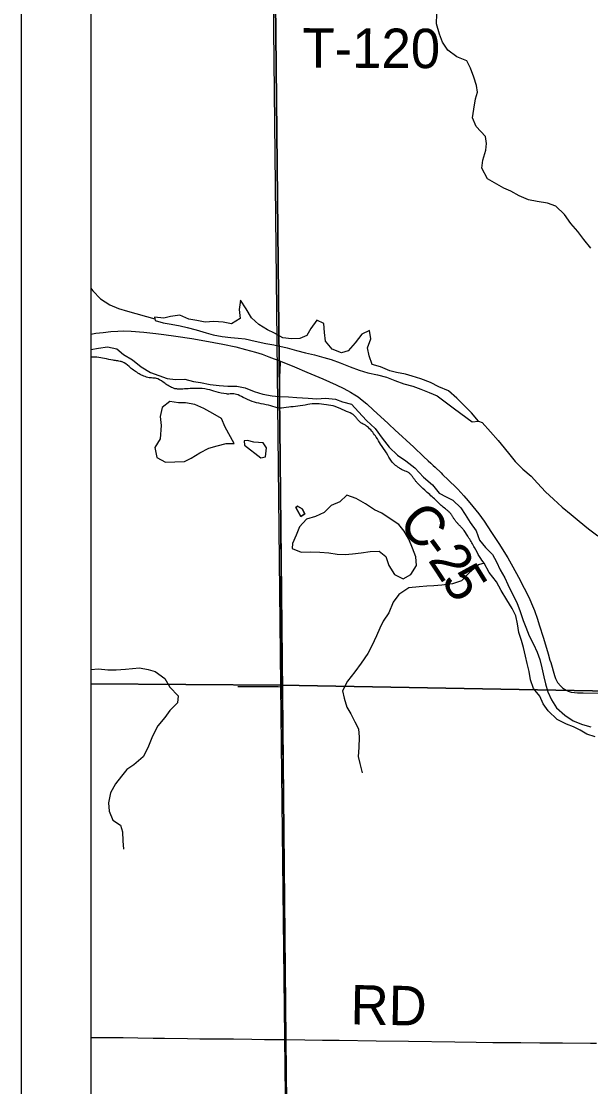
# Model space of a CAD drawing. Extents: x 0 to 1391, y -24 to 440.
# Drawn here: x 340 to 356.41, y 297.63 to 328.34 of the extents above; entities that cross this region are included whole.
import ezdxf

# ---------------------------------------------------------------- set-up
doc = ezdxf.new("R2010")
doc.units = 0
for name, color, linetype in [('GM_X_County_Road', 7, 'Continuous'), ('GM_X_County_Road_Text', 7, 'Continuous'), ('GM_X_Major_River', 7, 'Continuous'), ('GM_X_Minor_Lake', 7, 'Continuous'), ('GM_X_Minor_River', 7, 'Continuous'), ('GM_X_Section', 7, 'Continuous'), ('GM_X_Township', 7, 'Continuous'), ('GM_X_Township_Road', 7, 'Continuous'), ('GM_X_Township_Road_Text', 7, 'Continuous'), ('SH_Data', 7, 'Continuous')]:
    doc.layers.add(name, color=color, linetype=linetype)

msp = doc.modelspace()

# ---------------------------------------------------------------- linework, layer by layer
at = {"layer": 'GM_X_County_Road'}
for points in [[(342, 319.32), (342.146, 319.346), (342.355, 319.374), (342.577, 319.398), (342.787, 319.412), (342.96, 319.413), (343.17, 319.404), (343.528, 319.375), (343.874, 319.343), (344.108, 319.315), (344.452, 319.266), (344.919, 319.195), (345.286, 319.133), (345.811, 319.032), (346.187, 318.952), (346.464, 318.884), (346.751, 318.804), (346.94, 318.744), (347.138, 318.672), (347.476, 318.548)], [(347.522, 309.15), (347.51, 309.729), (347.5, 310.672), (347.493, 311.369), (347.495, 311.84), (347.492, 312.522), (347.487, 312.957), (347.484, 313.268), (347.481, 313.839), (347.481, 314.175), (347.481, 314.336), (347.48, 314.472), (347.475, 314.72), (347.472, 314.819), (347.467, 315.204), (347.459, 316.086), (347.454, 316.72), (347.451, 317.117), (347.45, 317.689), (347.452, 318.125), (347.459, 318.25), (347.476, 318.548)], [(347.476, 318.548), (347.874, 318.376), (348.231, 318.229), (348.688, 318.033), (349.075, 317.861), (349.298, 317.751), (349.485, 317.65), (349.614, 317.573), (349.708, 317.512), (349.828, 317.422), (349.962, 317.31), (350.156, 317.134), (350.565, 316.752), (350.601, 316.718), (350.766, 316.567), (351.312, 316.06), (351.596, 315.798), (351.732, 315.671), (351.804, 315.603), (351.875, 315.534), (351.93, 315.483), (352.101, 315.322), (352.142, 315.281), (352.184, 315.241), (352.28, 315.147), (352.579, 314.85), (352.759, 314.659), (352.883, 314.52), (353.019, 314.357), (353.186, 314.14), (353.339, 313.928), (353.557, 313.609), (353.765, 313.285), (354.021, 312.872), (354.172, 312.614), (354.334, 312.32), (354.5, 312), (354.637, 311.72), (354.708, 311.561), (354.79, 311.352), (354.878, 311.106), (354.932, 310.94), (355.05, 310.56), (355.184, 310.106), (355.236, 309.927), (355.26, 309.857), (355.366, 309.487), (355.399, 309.395), (355.434, 309.318), (355.459, 309.278), (355.555, 309.171), (355.599, 309.129), (355.657, 309.086), (355.709, 309.056), (355.762, 309.029), (355.854, 309.003), (355.951, 308.99), (356.036, 308.985), (356.197, 308.981), (356.657, 308.973)], [(347.627, 298.985), (347.626, 299.082), (347.613, 300.337), (347.603, 301.294), (347.598, 301.816), (347.586, 303.207), (347.579, 304.052), (347.574, 304.363), (347.566, 305.046), (347.565, 305.431), (347.56, 306.052), (347.551, 306.673), (347.536, 307.705), (347.533, 308.239), (347.532, 308.512), (347.524, 309.083), (347.522, 309.15)], [(347.727, 288.918), (347.727, 289.043), (347.723, 289.714), (347.709, 290.844), (347.702, 291.491), (347.694, 292.895), (347.684, 293.59), (347.674, 294.696), (347.656, 295.603), (347.651, 296.262), (347.635, 297.964), (347.629, 298.573), (347.627, 298.985)]]:
    msp.add_lwpolyline(points, dxfattribs=at)
at = {"layer": 'GM_X_Major_River'}
for points in [[(342, 318.879), (342.222, 318.918), (342.488, 318.952), (342.753, 318.902), (342.947, 318.74), (343.203, 318.577), (343.457, 318.383), (343.72, 318.212), (343.961, 318.132), (344.203, 318.045), (344.445, 318.018), (344.71, 318.022), (344.967, 317.957), (345.164, 317.931), (345.443, 317.873), (345.708, 317.846), (345.958, 317.82), (346.209, 317.823), (346.458, 317.774), (346.714, 317.671), (346.963, 317.591), (347.228, 317.542), (347.425, 317.523), (347.698, 317.519), (347.94, 317.5), (348.266, 317.479), (348.523, 317.46), (348.766, 317.479), (349.062, 317.444), (349.258, 317.372), (349.514, 317.308), (349.716, 317.084), (349.954, 316.83), (350.201, 316.598), (350.401, 316.322), (350.609, 316.068), (350.848, 315.836), (351.081, 315.673), (351.343, 315.464), (351.596, 315.201), (351.858, 314.977), (352.044, 314.739), (352.247, 314.629), (352.442, 314.535), (352.674, 314.318), (352.792, 314.119), (352.94, 313.889), (353.111, 313.651), (353.212, 313.384), (353.383, 313.176), (353.585, 312.975), (353.695, 312.761), (353.805, 312.531), (353.938, 312.301), (354.026, 312.102), (354.136, 311.865), (354.283, 311.582), (354.377, 311.33), (354.471, 311.063), (354.544, 310.872), (354.639, 310.627), (354.764, 310.39), (354.866, 310.153), (354.946, 309.946), (355.003, 309.703), (355.067, 309.443), (355.109, 309.238), (355.174, 309.009), (355.284, 308.779), (355.424, 308.549), (355.671, 308.34), (355.911, 308.177), (356.175, 308.066), (356.416, 308.002)], [(356.547, 307.713), (356.306, 307.794), (356.111, 307.911), (355.916, 307.999), (355.712, 308.078), (355.45, 308.213), (355.189, 308.46), (355.041, 308.668), (354.947, 308.882), (354.769, 309.106), (354.676, 309.358), (354.643, 309.602), (354.579, 309.831), (354.53, 310.037), (354.474, 310.288), (354.417, 310.494), (354.346, 310.723), (354.305, 310.975), (354.257, 311.203), (354.147, 311.418), (354, 311.663), (353.831, 311.932), (353.699, 312.185), (353.485, 312.455), (353.346, 312.716)]]:
    msp.add_lwpolyline(points, dxfattribs=at)
msp.add_spline([(353.346, 312.716), (353.213, 312.908), (353.066, 313.169), (352.905, 313.445), (352.765, 313.66), (352.709, 313.729), (352.648, 313.794), (352.586, 313.857), (352.528, 313.923), (352.483, 313.986), (352.442, 314.052), (352.4, 314.117), (352.35, 314.177), (352.291, 314.232), (352.228, 314.283), (352.104, 314.387), (351.911, 314.572), (351.635, 314.82), (351.419, 315.03), (351.363, 315.095), (351.313, 315.165), (351.262, 315.235), (351.204, 315.299), (351.141, 315.343), (351.069, 315.374), (350.995, 315.404), (350.927, 315.441), (350.857, 315.489), (350.789, 315.539), (350.673, 315.658), (350.526, 315.897), (350.357, 316.15), (350.232, 316.35), (350.009, 316.627), (349.952, 316.674), (349.888, 316.713), (349.823, 316.75), (349.762, 316.791), (349.705, 316.85), (349.653, 316.915), (349.598, 316.977), (349.532, 317.023), (349.321, 317.118), (349.051, 317.237), (348.794, 317.288), (348.521, 317.316), (348.256, 317.29), (347.967, 317.243), (347.708, 317.217), (347.435, 317.192), (347.193, 317.257), (346.914, 317.315), (346.657, 317.381), (346.394, 317.5), (346.199, 317.587), (346.13, 317.603), (346.057, 317.602), (345.983, 317.596), (345.911, 317.6), (345.616, 317.658), (345.368, 317.731), (345.065, 317.76), (344.807, 317.749), (344.606, 317.737), (344.505, 317.739), (344.455, 317.745), (344.405, 317.757), (344.265, 317.823), (344.135, 317.906), (343.933, 318.031), (343.865, 318.053), (343.791, 318.058), (343.717, 318.061), (343.646, 318.074), (343.571, 318.1), (343.498, 318.128), (343.36, 318.201), (343.106, 318.388), (342.911, 318.521), (342.878, 318.529), (342.846, 318.537), (342.779, 318.549), (342.647, 318.571), (342.398, 318.621), (342.178, 318.655), (342, 318.654)], degree=3, dxfattribs=at)
at = {"layer": 'GM_X_Minor_Lake'}
for p, q in [((352.995, 316.796), (353.177, 316.816)), ((346.426, 316.248), (346.438, 316.118))]:
    msp.add_line(p, q, dxfattribs=at)
for points in [[(353.177, 316.816), (352.976, 317.054), (352.767, 317.27), (352.559, 317.479), (352.319, 317.687), (352.033, 317.806), (351.8, 317.931), (351.513, 318.035), (351.272, 318.107), (351.076, 318.171), (350.819, 318.22), (350.622, 318.269), (350.351, 318.38), (350.117, 318.444), (350.03, 318.696), (349.981, 318.932), (350.076, 319.189), (350.042, 319.432), (349.813, 319.322), (349.627, 319.075), (349.418, 318.843), (349.228, 318.785), (348.964, 318.888), (348.77, 319.119), (348.737, 319.37), (348.718, 319.628), (348.522, 319.723), (348.344, 319.482), (348.235, 319.287), (348.028, 319.199), (347.793, 319.188), (347.536, 319.214), (347.295, 319.347), (347.1, 319.449), (346.852, 319.605), (346.635, 319.791), (346.48, 320.051), (346.317, 320.297), (346.282, 320.031), (346.309, 319.773), (346.056, 319.617), (345.822, 319.667), (345.549, 319.686), (345.298, 319.667), (345.064, 319.717), (344.829, 319.751), (344.566, 319.869), (344.3, 319.827), (344.11, 319.785), (343.837, 319.812)], [(343.837, 319.812), (343.858, 319.713), (344.085, 319.648), (344.319, 319.614), (344.584, 319.565), (344.78, 319.516), (345.037, 319.451), (345.331, 319.356), (345.527, 319.307), (345.792, 319.257), (346.042, 319.223), (346.254, 319.204), (346.451, 319.186), (346.745, 319.121), (347.048, 319.048), (347.275, 319.014), (347.668, 318.931), (347.932, 318.851), (348.196, 318.786), (348.453, 318.722), (348.717, 318.649), (348.929, 318.592), (349.193, 318.497), (349.479, 318.379), (349.735, 318.283), (349.992, 318.211), (350.264, 318.153), (350.528, 318.081), (350.769, 317.986), (351.026, 317.891), (351.282, 317.818), (351.516, 317.738), (351.757, 317.636), (351.991, 317.541), (352.485, 317.169), (352.995, 316.796)], [(346.133, 316.171), (345.872, 316.645), (345.771, 316.89), (345.524, 317.039), (345.261, 317.18), (345.006, 317.299), (344.734, 317.342), (344.536, 317.338), (344.279, 317.381), (344.064, 317.21), (344.006, 316.953), (344.031, 316.687), (344.001, 316.308)], [(344.001, 316.308), (343.852, 316.053), (343.907, 315.771), (344.154, 315.63), (344.427, 315.64), (344.708, 315.65), (344.9, 315.745), (345.145, 315.9), (345.406, 316.032), (345.65, 316.103), (345.901, 316.166), (346.133, 316.171)], [(347.039, 315.788), (347.066, 316.046), (346.971, 316.192), (346.706, 316.212), (346.524, 316.253), (346.426, 316.248)], [(346.438, 316.118), (346.901, 315.753), (347.039, 315.788)], [(351.04, 313.646), (350.884, 313.831), (350.636, 314.002), (350.396, 314.166), (350.185, 314.26), (349.923, 314.431), (349.652, 314.58), (349.381, 314.683), (349.18, 314.489), (348.928, 314.387), (348.728, 314.185), (348.483, 314.067), (348.224, 313.988), (348.024, 313.771), (347.921, 313.53), (347.818, 313.288), (347.809, 313.144)], [(347.966, 314.359), (347.912, 314.322), (348.059, 314.061)], [(348.059, 314.061), (347.912, 314.322), (347.966, 314.359), (348.094, 314.288), (348.174, 314.142), (348.059, 314.061)], [(348.059, 314.061), (348.174, 314.142), (348.094, 314.288), (347.966, 314.359)], [(347.809, 313.144), (348.065, 313.041), (348.323, 313.045), (348.603, 313.04), (348.861, 313.021), (349.103, 312.979), (349.338, 312.968), (349.543, 312.987), (349.794, 313.021), (350.06, 313.055), (350.318, 313.066), (350.512, 312.911), (350.591, 312.652), (350.754, 312.398), (351.01, 312.265), (351.232, 312.398), (351.395, 312.654), (351.377, 312.905), (351.275, 313.149), (351.173, 313.409), (351.04, 313.646)]]:
    msp.add_lwpolyline(points, dxfattribs=at)
at = {"layer": 'GM_X_Minor_River'}
for points in [[(356.419, 321.8), (356.213, 322.055), (356.044, 322.279), (355.845, 322.512), (355.654, 322.774), (355.41, 323.015), (355.169, 323.097), (354.867, 323.142), (354.618, 323.193), (354.356, 323.313), (354.109, 323.448), (353.906, 323.529), (353.704, 323.647), (353.443, 323.797), (353.276, 324.105), (353.304, 324.34), (353.394, 324.626), (353.406, 324.815), (353.381, 325.021), (353.115, 325.308), (353.007, 325.553), (353.044, 325.81), (353.096, 326.105), (353.146, 326.301), (353.121, 326.492), (353.043, 326.729), (352.951, 326.989), (352.842, 327.204), (352.557, 327.317), (352.296, 327.513), (352.142, 327.736), (352.057, 327.974), (351.966, 328.272), (351.98, 328.56)], [(342, 320.648), (342.065, 320.575), (342.287, 320.343), (342.548, 320.17), (342.803, 320.058), (343.059, 319.984), (343.849, 319.761)], [(353.177, 316.816), (353.282, 316.773), (353.526, 316.502), (353.747, 316.254), (353.924, 316.045), (354.086, 315.844), (354.24, 315.65), (354.462, 315.432), (354.7, 315.23), (354.877, 315.028), (355.114, 314.78), (355.344, 314.562), (355.588, 314.336), (355.848, 314.125), (356.086, 313.93), (356.346, 313.711), (356.622, 313.507)], [(353.346, 312.716), (353.178, 312.67), (352.924, 312.447), (352.685, 312.215), (352.433, 312.128), (352.122, 312.088), (351.894, 312.069), (351.689, 312.057), (351.469, 312.038), (351.173, 312.005), (350.881, 311.819), (350.718, 311.594), (350.592, 311.285), (350.429, 311.045), (350.335, 310.849), (350.24, 310.623), (350.106, 310.336), (349.989, 310.118), (349.795, 309.84), (349.616, 309.585), (349.4, 309.323), (349.259, 309.044), (349.308, 308.831), (349.387, 308.571), (349.498, 308.38), (349.616, 308.15), (349.718, 307.944), (349.737, 307.708), (349.732, 307.404), (349.713, 307.146), (349.763, 306.948), (349.827, 306.674)], [(342, 309.66), (342.003, 309.66), (342.223, 309.671), (342.496, 309.644), (342.739, 309.641), (343.005, 309.667), (343.21, 309.686), (343.407, 309.706), (343.657, 309.657), (343.86, 309.6), (344.138, 309.399), (344.285, 309.146), (344.524, 308.892), (344.498, 308.695), (344.282, 308.47), (344.142, 308.275), (343.933, 308.035), (343.784, 307.734), (343.65, 307.394), (343.517, 307.138), (343.248, 306.907), (343.041, 306.774), (342.886, 306.579), (342.716, 306.361), (342.567, 306.098), (342.517, 305.81), (342.528, 305.575), (342.638, 305.315), (342.863, 305.167), (342.913, 304.977), (342.924, 304.718), (342.95, 304.475)]]:
    msp.add_lwpolyline(points, dxfattribs=at)
at = {"layer": 'GM_X_Section'}
for p, q in [((342, 329.048), (342, 309.239)), ((342, 309.239), (342, 288.95))]:
    msp.add_line(p, q, dxfattribs=at)
for points in [[(342, 309.239), (347.482, 309.199), (347.266, 329.014), (346.743, 329.025), (342, 329.048)], [(342, 288.95), (347.709, 288.905), (347.482, 309.199), (342, 309.239)]]:
    msp.add_lwpolyline(points, dxfattribs=at)
for points in [[(366.91, 328.665), (367.258, 328.65), (367.565, 308.841), (347.482, 309.199), (347.266, 329.014)], [(347.482, 309.199), (367.565, 308.841), (367.728, 288.729), (347.709, 288.905)]]:
    msp.add_lwpolyline(points, close=True, dxfattribs=at)
at = {"layer": 'GM_X_Township'}
for points in [[(347.795, 282), (347.727, 288.944), (347.628, 298.991), (347.529, 308.991), (347.435, 318.551), (347.332, 328.904), (346.676, 328.912), (342, 328.905)], [(427.17, 329.098), (407.375, 328.93), (377.029, 328.672), (366.886, 328.586), (356.749, 328.811), (352.004, 328.845), (351.489, 328.852), (347.332, 328.904), (347.435, 318.551), (347.529, 308.991), (347.628, 298.991), (347.727, 288.944), (347.795, 282)], [(342, 328.905), (342, 282), (347.795, 282)]]:
    msp.add_lwpolyline(points, dxfattribs=at)
at = {"layer": 'GM_X_Township_Road'}
for points in [[(347.522, 309.15), (347.406, 309.151), (347.232, 309.152), (346.91, 309.154), (346.613, 309.159), (346.242, 309.158)], [(342, 299.052), (342.368, 299.048), (342.94, 299.046), (343.362, 299.042), (343.797, 299.032), (344.132, 299.024), (344.791, 299.019), (345.151, 299.013), (345.636, 299.009), (346.12, 299.006), (346.642, 298.996), (347.015, 298.991), (347.438, 298.988), (347.627, 298.985)], [(347.627, 298.985), (348.171, 298.977), (348.68, 298.971), (349.165, 298.966), (350.234, 298.952), (351.166, 298.945), (352.495, 298.923), (353.116, 298.912), (353.588, 298.902), (353.999, 298.9), (354.396, 298.899), (354.943, 298.893), (355.316, 298.893), (355.602, 298.893), (356.409, 298.888), (356.583, 298.887)]]:
    msp.add_lwpolyline(points, dxfattribs=at)
at = {"layer": 'SH_Data'}
for p, q in [((340, 420), (340, 280)), ((342, 418), (342, 282))]:
    msp.add_line(p, q, dxfattribs=at)

# ---------------------------------------------------------------- texts
at = {"layer": 'GM_X_County_Road_Text'}
for s, rotation, p in [('C', 313.4571, (350.82, 313.825)), ('2', 303.3393, (351.706, 312.813)), ('-', 306.3172, (351.438, 313.176)), ('5', 301.9304, (352.086, 312.234))]:
    msp.add_text(s, height=1.136, rotation=rotation, dxfattribs=at).set_placement(p)
at = {"layer": 'GM_X_Township_Road_Text'}
for s, rotation, p in [('T-120', 359.7136, (348.101, 327.007)), ('RD', 359.009, (349.483, 299.426))]:
    msp.add_text(s, height=1.1364, rotation=rotation, dxfattribs=at).set_placement(p)

doc.saveas('drawing.dxf')
